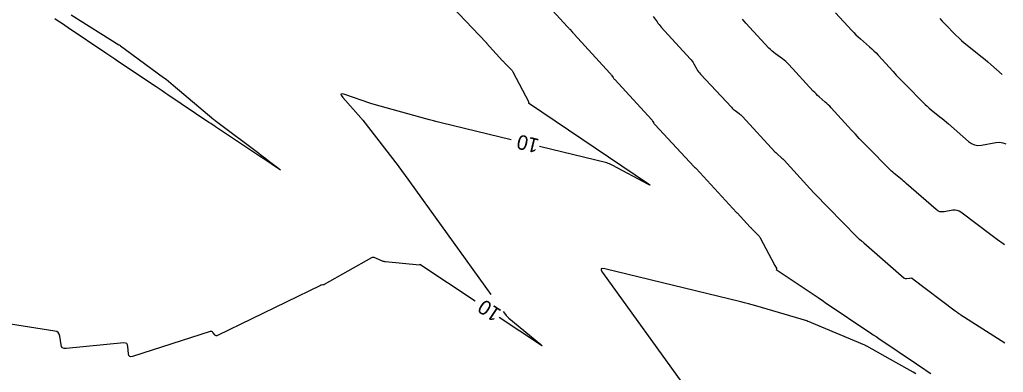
# Model space of a CAD drawing. Extents: x 1797789 to 1803805, y 249066 to 250293.
# Drawn here: x 1798010.2 to 1798416.4, y 249881.5 to 250027.1 of the extents above; entities that cross this region are included whole.
import ezdxf

# ---------------------------------------------------------------- set-up
doc = ezdxf.new("R2010")
doc.units = 0
doc.layers.add('33', color=7, linetype='Continuous')
doc.layers.add('34', color=7, linetype='Continuous')

msp = doc.modelspace()

# ---------------------------------------------------------------- linework, layer by layer
at = {"layer": '33'}
for points in [[(1798185.86, 250035.49), (1798202.79, 250017.7), (1798202.81, 250017.67), (1798202.83, 250017.65), (1798202.85, 250017.62), (1798202.87, 250017.6), (1798202.95, 250017.49), (1798202.97, 250017.47), (1798203, 250017.44), (1798203.02, 250017.41), (1798203.04, 250017.39), (1798209.66, 250010.14), (1798209.88, 250009.9), (1798210.11, 250009.66), (1798210.33, 250009.42), (1798210.56, 250009.18), (1798213.21, 250006.5), (1798213.41, 250006.28), (1798213.59, 250006.05), (1798213.76, 250005.81), (1798213.91, 250005.55), (1798220.46, 249993.07), (1798220.46, 249993.06), (1798220.47, 249993.05), (1798220.47, 249993.05), (1798220.33, 249992.84), (1798220.31, 249992.81), (1798220.31, 249992.78), (1798220.32, 249992.76), (1798220.34, 249992.74), (1798269.92, 249959.26), (1798270.42, 249958.9), (1798270.58, 249958.76), (1798270.38, 249958.83), (1798269.83, 249959.11), (1798254.88, 249967.08), (1798254.34, 249967.35), (1798253.79, 249967.58), (1798253.23, 249967.78), (1798252.65, 249967.93), (1798224.87, 249974.66)], [(1798390.16, 250027.55), (1798391.22, 250026.45), (1798392.29, 250025.36), (1798396.89, 250020.69), (1798398, 250019.59), (1798399.15, 250018.53), (1798400.33, 250017.5), (1798401.55, 250016.5), (1798406.46, 250012.59), (1798407.68, 250011.61), (1798408.89, 250010.61), (1798410.09, 250009.6), (1798411.27, 250008.57), (1798415.96, 250004.46)], [(1798213.21, 249977.48), (1798184.24, 249984.49), (1798182.67, 249984.88), (1798181.09, 249985.28), (1798179.52, 249985.7), (1798177.96, 249986.12), (1798156.62, 249992.03), (1798156.16, 249992.16), (1798155.7, 249992.3), (1798155.24, 249992.45), (1798154.78, 249992.61), (1798144.55, 249996.19), (1798143.39, 249996.5), (1798142.85, 249996.39), (1798142.95, 249995.85), (1798143.67, 249994.89), (1798151.11, 249986.5), (1798151.31, 249986.27), (1798151.5, 249986.05), (1798151.69, 249985.81), (1798151.87, 249985.58), (1798166.48, 249966.7), (1798167.05, 249965.95), (1798167.61, 249965.2), (1798168.17, 249964.45), (1798168.73, 249963.69), (1798204.83, 249913.72)], [(1798198.28, 249910.88), (1798175.51, 249926.07), (1798175.51, 249926.08), (1798175.51, 249926.08), (1798175.5, 249926.08), (1798175.5, 249926.07), (1798175.32, 249925.81), (1798175.32, 249925.81), (1798175.31, 249925.81), (1798175.3, 249925.81), (1798161.32, 249927.14), (1798161, 249927.19), (1798160.69, 249927.25), (1798160.38, 249927.34), (1798160.08, 249927.45), (1798156.59, 249928.89), (1798156.31, 249928.97), (1798156.04, 249928.99), (1798155.77, 249928.94), (1798155.5, 249928.82), (1798135.91, 249917.76), (1798135.8, 249917.7), (1798135.67, 249917.66), (1798135.55, 249917.63), (1798135.41, 249917.61), (1798134.88, 249917.57), (1798134.75, 249917.55), (1798134.62, 249917.52), (1798134.5, 249917.48), (1798134.37, 249917.43), (1798091.93, 249896.7), (1798091.63, 249896.6), (1798091.36, 249896.61), (1798091.11, 249896.72), (1798090.88, 249896.93), (1798090.02, 249898.01), (1798089.79, 249898.23), (1798089.54, 249898.35), (1798089.25, 249898.39), (1798088.94, 249898.33), (1798056.79, 249888.1), (1798056.13, 249887.99), (1798055.65, 249888.13), (1798055.33, 249888.53), (1798055.17, 249889.17), (1798054.89, 249892.26), (1798054.73, 249892.92), (1798054.4, 249893.38), (1798053.89, 249893.62), (1798053.21, 249893.65), (1798029.35, 249891.31), (1798028.55, 249891.34), (1798027.93, 249891.62), (1798027.51, 249892.15), (1798027.29, 249892.92), (1798026.76, 249896.49), (1798026.53, 249897.29), (1798026.11, 249897.91), (1798025.51, 249898.33), (1798024.71, 249898.56), (1798006.39, 249901.46)], [(1798209.91, 249906.69), (1798210.88, 249905.35), (1798211.18, 249904.96), (1798211.5, 249904.6), (1798211.84, 249904.25), (1798212.21, 249903.93), (1798225.42, 249892.97), (1798225.89, 249892.57), (1798226.03, 249892.41), (1798225.84, 249892.5), (1798225.32, 249892.83), (1798208.26, 249904.22)]]:
    msp.add_lwpolyline(points, dxfattribs=at)
at = {"layer": '34'}
for points in [[(1798222.37, 250039.57), (1798236.48, 250024.11), (1798236.71, 250023.86), (1798236.94, 250023.6), (1798237.17, 250023.35), (1798237.4, 250023.1), (1798238.33, 250022.08), (1798238.56, 250021.83), (1798238.79, 250021.58), (1798239.02, 250021.32), (1798239.25, 250021.07), (1798253.91, 250005), (1798254.1, 250004.79), (1798254.28, 250004.58), (1798254.45, 250004.36), (1798254.61, 250004.13), (1798255.24, 250003.21), (1798255.4, 250002.99), (1798255.57, 250002.77), (1798255.75, 250002.55), (1798255.94, 250002.34), (1798271.24, 249985.7), (1798271.37, 249985.54), (1798271.5, 249985.38), (1798271.61, 249985.21), (1798271.71, 249985.04), (1798272.11, 249984.32), (1798272.22, 249984.15), (1798272.33, 249983.98), (1798272.46, 249983.82), (1798272.59, 249983.67), (1798288.64, 249966.43), (1798288.72, 249966.35), (1798288.8, 249966.28), (1798288.88, 249966.21), (1798288.96, 249966.15), (1798289.31, 249965.89), (1798289.4, 249965.83), (1798289.48, 249965.76), (1798289.56, 249965.68), (1798289.63, 249965.61), (1798306.27, 249947.56), (1798306.29, 249947.54), (1798306.31, 249947.52), (1798306.33, 249947.5), (1798306.35, 249947.48), (1798306.44, 249947.41), (1798306.46, 249947.39), (1798306.48, 249947.37), (1798306.5, 249947.35), (1798306.52, 249947.33), (1798311.92, 249941.44), (1798312.1, 249941.24), (1798312.29, 249941.05), (1798312.47, 249940.86), (1798312.66, 249940.66), (1798315.31, 249937.98), (1798315.55, 249937.72), (1798315.77, 249937.44), (1798315.97, 249937.14), (1798316.15, 249936.83), (1798321.76, 249926.13), (1798321.83, 249926.01), (1798321.9, 249925.88), (1798321.97, 249925.76), (1798322.04, 249925.64), (1798322.86, 249924.31), (1798322.86, 249924.31), (1798322.87, 249924.3), (1798322.87, 249924.3), (1798322.87, 249924.29), (1798322.87, 249924.29), (1798322.87, 249924.29), (1798322.69, 249924.03), (1798322.69, 249924.02), (1798322.69, 249924.02), (1798322.69, 249924.02), (1798322.69, 249924.02), (1798339.9, 249912.41), (1798340.95, 249911.7), (1798342.01, 249910.99), (1798343.06, 249910.28), (1798344.11, 249909.57), (1798360.51, 249898.52), (1798361.63, 249897.77), (1798362.74, 249897.02), (1798363.86, 249896.27), (1798364.97, 249895.52), (1798380.53, 249885.06), (1798382.01, 249884.07), (1798383.49, 249883.08), (1798384.97, 249882.08), (1798386.45, 249881.09)], [(1798347.06, 250029.95), (1798353.81, 250022.62), (1798354.67, 250021.72), (1798355.55, 250020.84), (1798356.46, 250019.99), (1798357.39, 250019.16), (1798361.15, 250015.89), (1798362.08, 250015.06), (1798362.98, 250014.2), (1798363.86, 250013.32), (1798364.72, 250012.41), (1798370.91, 250005.66), (1798372.23, 250004.23), (1798373.56, 250002.82), (1798374.9, 250001.42), (1798376.26, 250000.03), (1798383.3, 249992.89), (1798384.11, 249992.09), (1798384.95, 249991.31), (1798385.81, 249990.56), (1798386.7, 249989.83), (1798390.28, 249986.98), (1798391.17, 249986.26), (1798392.05, 249985.54), (1798392.93, 249984.8), (1798393.79, 249984.05), (1798402.07, 249976.79), (1798403.26, 249975.94), (1798404.54, 249975.41), (1798405.91, 249975.2), (1798407.36, 249975.3), (1798413.36, 249976.36), (1798414.83, 249976.47), (1798416.22, 249976.29), (1798417.54, 249975.82)], [(1798031.44, 250029.03), (1798051.11, 250016.75), (1798051.3, 250016.62), (1798051.5, 250016.49), (1798051.69, 250016.36), (1798051.88, 250016.23), (1798069.64, 250003.24), (1798070.66, 250002.47), (1798071.67, 250001.69), (1798072.66, 250000.89), (1798073.64, 250000.08), (1798090.4, 249985.84), (1798090.44, 249985.81), (1798090.48, 249985.78), (1798090.51, 249985.75), (1798090.55, 249985.73), (1798090.78, 249985.56), (1798090.87, 249985.5), (1798090.88, 249985.49), (1798090.9, 249985.48), (1798090.91, 249985.47), (1798090.93, 249985.46), (1798108.97, 249971.96), (1798109.95, 249971.21), (1798110.93, 249970.47), (1798111.91, 249969.72), (1798112.88, 249968.96), (1798117.2, 249965.59), (1798117.76, 249965.14), (1798117.94, 249964.97), (1798117.72, 249965.09), (1798117.12, 249965.48), (1798110.99, 249969.58), (1798110.76, 249969.73), (1798110.54, 249969.88), (1798110.31, 249970.03), (1798110.08, 249970.18), (1798091.13, 249982.87), (1798090.45, 249983.33), (1798089.76, 249983.79), (1798089.08, 249984.25), (1798088.39, 249984.7), (1798071.4, 249996.1), (1798070.2, 249996.9), (1798068.99, 249997.71), (1798067.79, 249998.51), (1798066.59, 249999.32), (1798050.67, 250010), (1798049.45, 250010.82), (1798048.23, 250011.64), (1798047.02, 250012.45), (1798045.8, 250013.27), (1798030.24, 250023.73), (1798028.86, 250024.65), (1798027.48, 250025.58), (1798026.11, 250026.5), (1798024.73, 250027.43)], [(1798271.85, 250028.44), (1798273.42, 250026.17), (1798273.82, 250025.6), (1798274.24, 250025.06), (1798274.68, 250024.53), (1798275.14, 250024.01), (1798287.17, 250010.92), (1798287.58, 250010.45), (1798287.97, 250009.95), (1798288.32, 250009.42), (1798288.64, 250008.88), (1798289.88, 250006.66), (1798290.2, 250006.12), (1798290.56, 250005.6), (1798290.94, 250005.1), (1798291.36, 250004.63), (1798304.14, 249990.9), (1798304.49, 249990.54), (1798304.86, 249990.2), (1798305.24, 249989.88), (1798305.64, 249989.57), (1798307.28, 249988.39), (1798307.68, 249988.08), (1798308.06, 249987.76), (1798308.43, 249987.42), (1798308.78, 249987.05), (1798322.12, 249972.58), (1798322.42, 249972.27), (1798322.73, 249971.96), (1798323.04, 249971.66), (1798323.36, 249971.38), (1798324.68, 249970.24), (1798325, 249969.95), (1798325.31, 249969.65), (1798325.62, 249969.34), (1798325.92, 249969.03), (1798336.57, 249957.41), (1798338.45, 249955.37), (1798340.35, 249953.36), (1798342.27, 249951.36), (1798344.21, 249949.37), (1798356.13, 249937.28), (1798356.34, 249937.08), (1798356.55, 249936.88), (1798356.78, 249936.68), (1798357, 249936.5), (1798357.93, 249935.76), (1798358.16, 249935.58), (1798358.39, 249935.39), (1798358.61, 249935.2), (1798358.84, 249935), (1798375.31, 249920.56), (1798375.58, 249920.36), (1798375.87, 249920.24), (1798376.18, 249920.2), (1798376.51, 249920.22), (1798377.88, 249920.46), (1798378.21, 249920.49), (1798378.53, 249920.45), (1798378.83, 249920.34), (1798379.11, 249920.16), (1798396.51, 249906.95), (1798396.71, 249906.8), (1798396.91, 249906.65), (1798397.11, 249906.5), (1798397.31, 249906.35), (1798398.12, 249905.76), (1798398.32, 249905.61), (1798398.53, 249905.47), (1798398.73, 249905.33), (1798398.94, 249905.2), (1798417.08, 249893.76)], [(1798416.89, 249934.09), (1798416.32, 249934.5), (1798414.03, 249936.18), (1798413.46, 249936.6), (1798412.9, 249937.02), (1798412.33, 249937.44), (1798411.77, 249937.87), (1798398.95, 249947.6), (1798398.18, 249948.08), (1798397.37, 249948.37), (1798396.52, 249948.48), (1798395.62, 249948.41), (1798391.94, 249947.76), (1798391.04, 249947.7), (1798390.21, 249947.83), (1798389.42, 249948.15), (1798388.69, 249948.67), (1798376.31, 249959.52), (1798375.77, 249960), (1798375.22, 249960.46), (1798374.67, 249960.92), (1798374.1, 249961.37), (1798371.85, 249963.17), (1798371.3, 249963.62), (1798370.75, 249964.09), (1798370.23, 249964.58), (1798369.71, 249965.09), (1798360.24, 249974.7), (1798358.59, 249976.39), (1798356.96, 249978.09), (1798355.34, 249979.8), (1798353.74, 249981.53), (1798345.32, 249990.72), (1798344.74, 249991.33), (1798344.15, 249991.93), (1798343.54, 249992.5), (1798342.91, 249993.06), (1798340.37, 249995.27), (1798339.75, 249995.83), (1798339.14, 249996.4), (1798338.54, 249996.99), (1798337.97, 249997.6), (1798327.92, 250008.5), (1798327.29, 250009.15), (1798326.64, 250009.76), (1798325.95, 250010.34), (1798325.24, 250010.88), (1798322.33, 250013), (1798321.61, 250013.54), (1798320.93, 250014.12), (1798320.27, 250014.73), (1798319.64, 250015.37), (1798310.13, 250025.58), (1798309.43, 250026.38), (1798308.78, 250027.22)], [(1798380.36, 249880.87), (1798379.17, 249881.56), (1798371.99, 249885.61), (1798360.13, 249892.29), (1798359.92, 249892.4), (1798359.71, 249892.51), (1798359.5, 249892.61), (1798359.28, 249892.71), (1798337.22, 249902.01), (1798336.73, 249902.21), (1798336.24, 249902.39), (1798335.75, 249902.56), (1798335.25, 249902.72), (1798314.25, 249908.98), (1798312.7, 249909.43), (1798311.15, 249909.86), (1798309.59, 249910.27), (1798308.03, 249910.66), (1798251.89, 249924.25), (1798250.89, 249924.38), (1798250.39, 249924.18), (1798250.4, 249923.65), (1798250.9, 249922.77), (1798285.52, 249874.86)]]:
    msp.add_lwpolyline(points, dxfattribs=at)

# ---------------------------------------------------------------- texts
at = {"layer": '33'}
for rotation, p in [(166.3923, (1798225.1, 249977.69)), (146.2773, (1798209.51, 249906.99))]:
    msp.add_text('10', height=6, rotation=rotation, dxfattribs=at).set_placement(p)

doc.saveas('drawing.dxf')
